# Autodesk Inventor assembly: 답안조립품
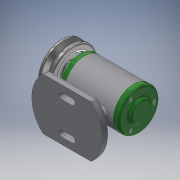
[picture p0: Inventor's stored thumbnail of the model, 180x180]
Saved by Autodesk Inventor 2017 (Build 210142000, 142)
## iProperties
Part Number: 답안조립품
Material: 일반
Document SubType Name: Assembly
Designer: 601-13
Author: 601-13
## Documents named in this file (14)
- C:\Users\601-13\Desktop\720206V1003\답안조립품.iam
- C:\Users\601-13\Desktop\720206V1003\본체.ipt
- C:\Users\601-13\Desktop\720206V1003\V벨트풀리.ipt
- C:\Users\601-13\Desktop\720206V1003\고무 캡.ipt
- C:\Users\601-13\Desktop\720206V1003\너트 M8.ipt
- C:\Users\601-13\Desktop\720206V1003\뒤커버.ipt
- C:\Users\601-13\Desktop\720206V1003\베어링 6002.ipt
- C:\Users\601-13\Desktop\720206V1003\볼트 M4 x 10.ipt
- C:\Users\601-13\Desktop\720206V1003\스프링와셔 8.ipt
- C:\Users\601-13\Desktop\720206V1003\앞커버.ipt
- C:\Users\601-13\Desktop\720206V1003\오일 실 15 x 25 x 7.ipt
- C:\Users\601-13\Desktop\720206V1003\축.ipt
- C:\Users\601-13\Desktop\720206V1003\키 3 x 3 x 12.ipt
- C:\Users\601-13\Desktop\720206V1003\평와셔 8 x 17.ipt
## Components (2 placed, 2 different names)
1. V벨트풀리:1 — 각도:1
2. 고무 캡:1
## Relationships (1: Angle 1)
- 각도:1 [Angle]: V벨트풀리:1
